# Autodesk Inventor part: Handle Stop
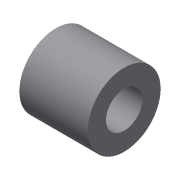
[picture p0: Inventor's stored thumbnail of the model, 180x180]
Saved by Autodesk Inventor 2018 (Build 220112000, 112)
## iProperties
Shininess: 77.0
Length Units: 11269
Angle Units: 11279
Time Units: 11290
Mass Units: 11283
Length Display Precision: 3
Angle Display Precision: 2
Compacted: True
Created: 2002-02
Part Number: Handle Stop
Document SubType Name: Modeling
Designer: ***
Density: 1 g/cm^3
Material: Generic
Mass: 2.36248 g
Surface Area: 14.8283 cm^2
Volume: 2.36248 cm^3
Appearance: Default
Density: 0.0
Volumn: 0.0
Area: 0.0
PropertySet Name: Model Information
Control State: 0
Master: False
Checked Out: False
Author: ***
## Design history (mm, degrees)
sketch "Sketch1"
  geometry: L1 (0, 0)-(0, -2); L2 (0, -2)-(8, -2); L3 (8, -2)-(8, 13); L4 (8, 13)-(4, 13); L5 (4, 13)-(4, 0); L6 (4, 0)-(0, 0)
  constraints: 12 end point, 4 parallel, 1 perpendicular, 1 vertical
  dimensions: "d0" = 16 diameter of L3 L1; "d1" = 8 diameter of L5 L1; "d2" = 2 distance of L1.start L1.end; "d3" = 15 distance of L2.end L3.end
revolve "Revolution1" sketch "Sketch1" stored, may be unused: angle "d4" = 90 deg
body "Solid1"
